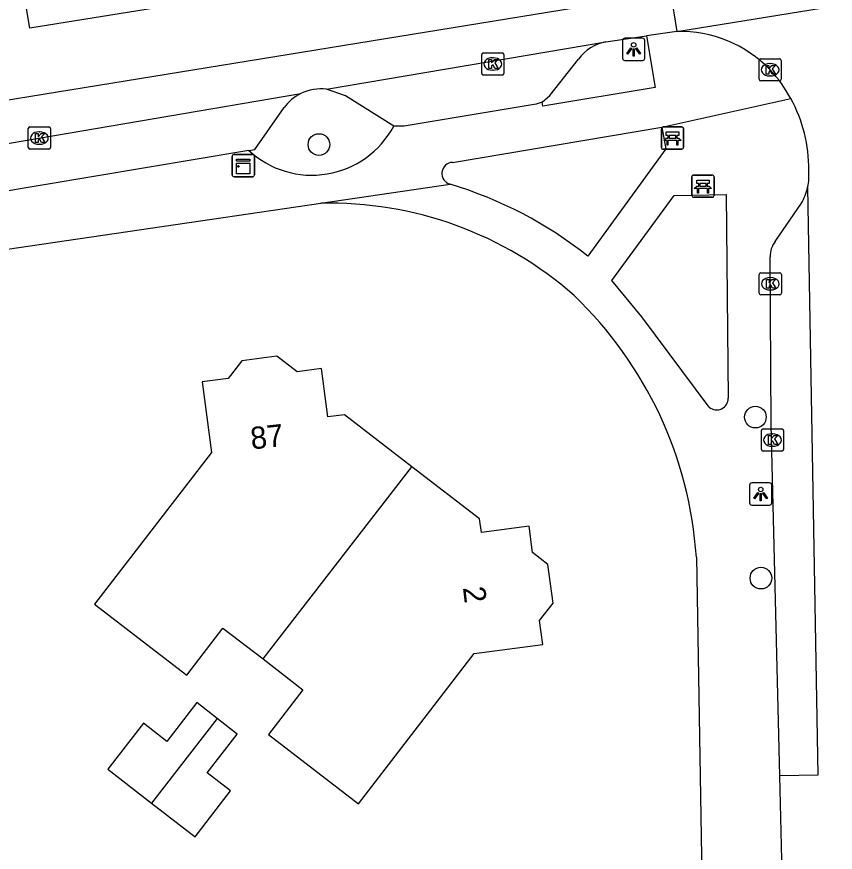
# Model space of a CAD drawing. Extents: x 161772 to 163123, y 383092 to 383917.
# Drawn here: x 162243.1 to 162280.01, y 383587.85 to 383625.53 of the extents above; entities that cross this region are included whole.
import ezdxf

# ---------------------------------------------------------------- set-up
doc = ezdxf.new("R2010")
doc.units = 0
for name, color, linetype in [('IMGEO_Bank', 7, 'Continuous'), ('IMGEO_Boom', 7, 'Continuous'), ('IMGEO_Kast', 7, 'Continuous'), ('IMGEO_Kolk', 7, 'Continuous'), ('IMGEO_Lichtpunt', 7, 'Continuous'), ('IMGEO_Pand', 7, 'Continuous'), ('IMGEO_Pand_nummerreeks', 7, 'Continuous'), ('IMGEO_Parkeervlak_open', 7, 'Continuous'), ('IMGEO_Rijbaan_lokaal_gesloten', 7, 'Continuous'), ('IMGEO_Voetpad_open', 7, 'Continuous')]:
    doc.layers.add(name, color=color, linetype=linetype)

msp = doc.modelspace()

# ---------------------------------------------------------------- linework, layer by layer
at = {"layer": 'IMGEO_Bank'}
for p, q in [((162272.166, 383619.631), (162272.166, 383620.472)), ((162272.166, 383620.472), (162272.166, 383619.631)), ((162272.241, 383620.556), (162273.082, 383620.556)), ((162273.082, 383620.556), (162272.241, 383620.556)), ((162273.166, 383620.481), (162273.166, 383619.64)), ((162273.166, 383619.64), (162273.166, 383620.481)), ((162272.475, 383620.062), (162272.475, 383620.168)), ((162272.519, 383620.168), (162272.519, 383620.062)), ((162272.807, 383620.174), (162272.525, 383620.174)), ((162272.525, 383620.056), (162272.807, 383620.056)), ((162272.813, 383620.062), (162272.813, 383620.168)), ((162272.857, 383620.168), (162272.857, 383620.062)), ((162272.863, 383619.954), (162272.47, 383619.954)), ((162273.091, 383619.556), (162272.25, 383619.556)), ((162272.25, 383619.556), (162273.091, 383619.556)), ((162273.54, 383617.46), (162273.54, 383618.301)), ((162273.54, 383618.301), (162273.54, 383617.46)), ((162273.615, 383618.385), (162274.456, 383618.385)), ((162274.456, 383618.385), (162273.615, 383618.385)), ((162274.54, 383618.31), (162274.54, 383617.469)), ((162274.54, 383617.469), (162274.54, 383618.31)), ((162274.237, 383617.783), (162273.844, 383617.783)), ((162273.849, 383617.891), (162273.849, 383617.997)), ((162273.893, 383617.997), (162273.893, 383617.891)), ((162274.181, 383618.003), (162273.899, 383618.003)), ((162273.899, 383617.885), (162274.181, 383617.885)), ((162274.187, 383617.891), (162274.187, 383617.997)), ((162274.231, 383617.997), (162274.231, 383617.891)), ((162274.465, 383617.385), (162273.624, 383617.385)), ((162273.624, 383617.385), (162274.465, 383617.385))]:
    msp.add_line(p, q, dxfattribs=at)
for points in [[(162272.413, 383619.954), (162272.271, 383619.954), (162272.383, 383620.056), (162272.469, 383620.056)], [(162272.469, 383620.174), (162272.383, 383620.174), (162272.383, 383620.335), (162272.946, 383620.335), (162272.946, 383620.174), (162272.863, 383620.174)], [(162272.863, 383620.056), (162272.946, 383620.056), (162273.058, 383619.954), (162272.919, 383619.954)], [(162272.463, 383619.947), (162272.463, 383619.74), (162272.42, 383619.74), (162272.42, 383619.947)], [(162272.913, 383619.947), (162272.913, 383619.74), (162272.869, 383619.74), (162272.869, 383619.947)], [(162273.843, 383618.003), (162273.757, 383618.003), (162273.757, 383618.164), (162274.32, 383618.164), (162274.32, 383618.003), (162274.237, 383618.003)], [(162273.787, 383617.783), (162273.645, 383617.783), (162273.757, 383617.885), (162273.843, 383617.885)], [(162273.837, 383617.776), (162273.837, 383617.569), (162273.794, 383617.569), (162273.794, 383617.776)], [(162274.237, 383617.885), (162274.32, 383617.885), (162274.432, 383617.783), (162274.293, 383617.783)], [(162274.287, 383617.776), (162274.287, 383617.569), (162274.243, 383617.569), (162274.243, 383617.776)]]:
    msp.add_lwpolyline(points, dxfattribs=at)
for centre, radius, start, end in [((162272.244, 383620.478), 0.0779, 92.4484, 184.2845), ((162272.244, 383620.478), 0.0779, 92.4484, 184.2845), ((162273.088, 383620.478), 0.0779, 2.4484, 94.2845), ((162273.088, 383620.478), 0.0779, 2.4484, 94.2845), ((162272.468, 383620.167), 0.00671, 2.8957, 87.1043), ((162272.468, 383620.063), 0.00671, 272.8957, 357.1043), ((162272.525, 383620.167), 0.00671, 92.8957, 177.1043), ((162272.525, 383620.063), 0.00671, 182.8957, 267.1043), ((162272.807, 383620.167), 0.00671, 2.8957, 87.1043), ((162272.807, 383620.063), 0.00671, 272.8957, 357.1043), ((162272.864, 383620.167), 0.00671, 92.8957, 177.1043), ((162272.864, 383620.063), 0.00671, 182.8957, 267.1043), ((162272.244, 383619.634), 0.0779, 182.4484, 274.2845), ((162272.244, 383619.634), 0.0779, 182.4484, 274.2845), ((162272.413, 383619.947), 0.00671, 2.8957, 87.1043), ((162272.47, 383619.947), 0.00671, 92.8957, 177.1043), ((162272.862, 383619.947), 0.00671, 2.8957, 87.1043), ((162272.919, 383619.947), 0.00671, 92.8957, 177.1043), ((162273.088, 383619.634), 0.0779, 272.4484, 4.2845), ((162273.088, 383619.634), 0.0779, 272.4484, 4.2845), ((162273.618, 383618.307), 0.0779, 92.4484, 184.2845), ((162273.618, 383618.307), 0.0779, 92.4484, 184.2845), ((162274.462, 383618.307), 0.0779, 2.4484, 94.2845), ((162274.462, 383618.307), 0.0779, 2.4484, 94.2845), ((162273.787, 383617.776), 0.00671, 2.8957, 87.1043), ((162273.844, 383617.776), 0.00671, 92.8957, 177.1043), ((162273.842, 383617.996), 0.00671, 2.8957, 87.1043), ((162273.842, 383617.892), 0.00671, 272.8957, 357.1043), ((162273.899, 383617.996), 0.00671, 92.8957, 177.1043), ((162273.899, 383617.892), 0.00671, 182.8957, 267.1043), ((162274.181, 383617.996), 0.00671, 2.8957, 87.1043), ((162274.181, 383617.892), 0.00671, 272.8957, 357.1043), ((162274.238, 383617.996), 0.00671, 92.8957, 177.1043), ((162274.238, 383617.892), 0.00671, 182.8957, 267.1043), ((162274.236, 383617.776), 0.00671, 2.8957, 87.1043), ((162274.293, 383617.776), 0.00671, 92.8957, 177.1043), ((162273.618, 383617.463), 0.0779, 182.4484, 274.2845), ((162273.618, 383617.463), 0.0779, 182.4484, 274.2845), ((162274.462, 383617.463), 0.0779, 272.4484, 4.2845), ((162274.462, 383617.463), 0.0779, 272.4484, 4.2845)]:
    msp.add_arc(centre, radius, start, end, dxfattribs=at)
at = {"layer": 'IMGEO_Boom'}
for centre in [(162256.725, 383619.765), (162276.403, 383607.472), (162276.656, 383600.211)]:
    msp.add_circle(centre, 0.489, dxfattribs=at)
at = {"layer": 'IMGEO_Kast'}
for p, q in [((162252.811, 383618.388), (162252.811, 383619.229)), ((162252.811, 383619.229), (162252.811, 383618.388)), ((162252.886, 383619.313), (162253.727, 383619.313)), ((162253.727, 383619.313), (162252.886, 383619.313)), ((162253.811, 383619.238), (162253.811, 383618.397)), ((162253.811, 383618.397), (162253.811, 383619.238)), ((162253.736, 383618.313), (162252.895, 383618.313)), ((162252.895, 383618.313), (162253.736, 383618.313))]:
    msp.add_line(p, q, dxfattribs=at)
for points in [[(162253.006, 383619.103), (162253.606, 383619.103), (162253.606, 383619.018), (162253.006, 383619.018), (162253.006, 383619.103)], [(162253.006, 383618.928), (162253.606, 383618.928), (162253.606, 383618.439), (162253.006, 383618.439), (162253.006, 383618.928)]]:
    msp.add_lwpolyline(points, dxfattribs=at)
msp.add_circle((162253.09, 383618.777), 0.0377, dxfattribs=at)
for centre, start, end in [((162252.889, 383619.235), 92.4484, 184.2845), ((162252.889, 383619.235), 92.4484, 184.2845), ((162253.733, 383619.235), 2.4484, 94.2845), ((162253.733, 383619.235), 2.4484, 94.2845), ((162252.889, 383618.391), 182.4484, 274.2845), ((162252.889, 383618.391), 182.4484, 274.2845), ((162253.733, 383618.391), 272.4484, 4.2845), ((162253.733, 383618.391), 272.4484, 4.2845)]:
    msp.add_arc(centre, 0.0779, start, end, dxfattribs=at)
at = {"layer": 'IMGEO_Kolk'}
for p, q in [((162264.065, 383622.971), (162264.065, 383623.823)), ((162264.14, 383623.897), (162264.992, 383623.897)), ((162265.066, 383623.823), (162265.066, 383622.971)), ((162264.553, 383623.677), (162264.578, 383623.677)), ((162276.568, 383622.71), (162276.568, 383623.562)), ((162276.643, 383623.636), (162277.495, 383623.636)), ((162277.056, 383623.416), (162277.081, 383623.416)), ((162277.569, 383623.562), (162277.569, 383622.71)), ((162264.576, 383623.117), (162264.551, 383623.117)), ((162264.992, 383622.897), (162264.14, 383622.897)), ((162277.495, 383622.636), (162276.643, 383622.636)), ((162277.079, 383622.856), (162277.054, 383622.856)), ((162243.618, 383619.632), (162243.618, 383620.484)), ((162243.693, 383620.558), (162244.545, 383620.558)), ((162244.619, 383620.484), (162244.619, 383619.632)), ((162244.106, 383620.338), (162244.131, 383620.338)), ((162244.129, 383619.778), (162244.104, 383619.778)), ((162244.545, 383619.558), (162243.693, 383619.558)), ((162276.653, 383613.985), (162277.505, 383613.985)), ((162276.578, 383613.059), (162276.578, 383613.911)), ((162277.066, 383613.765), (162277.091, 383613.765)), ((162277.579, 383613.911), (162277.579, 383613.059)), ((162277.089, 383613.205), (162277.064, 383613.205)), ((162277.505, 383612.985), (162276.653, 383612.985)), ((162276.673, 383606.012), (162276.673, 383606.864)), ((162276.748, 383606.938), (162277.6, 383606.938)), ((162277.674, 383606.864), (162277.674, 383606.012)), ((162277.161, 383606.718), (162277.186, 383606.718)), ((162277.184, 383606.158), (162277.159, 383606.158)), ((162277.6, 383605.938), (162276.748, 383605.938))]:
    msp.add_line(p, q, dxfattribs=at)
for points in [[(162264.065, 383622.971), (162264.065, 383623.823)], [(162264.14, 383623.897), (162264.992, 383623.897)], [(162265.066, 383623.823), (162265.066, 383622.971)], [(162264.386, 383623.597), (162264.509, 383623.597), (162264.509, 383623.446), (162264.639, 383623.597), (162264.803, 383623.597), (162264.657, 383623.446), (162264.81, 383623.197), (162264.658, 383623.197), (162264.573, 383623.361), (162264.509, 383623.294), (162264.509, 383623.197), (162264.386, 383623.197), (162264.386, 383623.597)], [(162276.568, 383622.71), (162276.568, 383623.562)], [(162276.643, 383623.636), (162277.495, 383623.636)], [(162277.569, 383623.562), (162277.569, 383622.71)], [(162276.889, 383623.336), (162277.012, 383623.336), (162277.012, 383623.185), (162277.142, 383623.336), (162277.306, 383623.336), (162277.16, 383623.185), (162277.313, 383622.936), (162277.161, 383622.936), (162277.076, 383623.1), (162277.012, 383623.033), (162277.012, 383622.936), (162276.889, 383622.936), (162276.889, 383623.336)], [(162264.992, 383622.897), (162264.14, 383622.897)], [(162277.495, 383622.636), (162276.643, 383622.636)], [(162243.618, 383619.632), (162243.618, 383620.484)], [(162243.693, 383620.558), (162244.545, 383620.558)], [(162244.619, 383620.484), (162244.619, 383619.632)], [(162243.939, 383620.258), (162244.062, 383620.258), (162244.062, 383620.107), (162244.192, 383620.258), (162244.356, 383620.258), (162244.21, 383620.107), (162244.363, 383619.858), (162244.211, 383619.858), (162244.126, 383620.022), (162244.062, 383619.955), (162244.062, 383619.858), (162243.939, 383619.858), (162243.939, 383620.258)], [(162244.545, 383619.558), (162243.693, 383619.558)], [(162276.653, 383613.985), (162277.505, 383613.985)], [(162276.578, 383613.059), (162276.578, 383613.911)], [(162276.899, 383613.685), (162277.022, 383613.685), (162277.022, 383613.534), (162277.152, 383613.685), (162277.316, 383613.685), (162277.17, 383613.534), (162277.323, 383613.285), (162277.171, 383613.285), (162277.086, 383613.449), (162277.022, 383613.382), (162277.022, 383613.285), (162276.899, 383613.285), (162276.899, 383613.685)], [(162277.579, 383613.911), (162277.579, 383613.059)], [(162277.505, 383612.985), (162276.653, 383612.985)], [(162276.673, 383606.012), (162276.673, 383606.864)], [(162276.748, 383606.938), (162277.6, 383606.938)], [(162277.674, 383606.864), (162277.674, 383606.012)], [(162276.994, 383606.638), (162277.117, 383606.638), (162277.117, 383606.487), (162277.247, 383606.638), (162277.411, 383606.638), (162277.265, 383606.487), (162277.418, 383606.238), (162277.266, 383606.238), (162277.181, 383606.402), (162277.117, 383606.335), (162277.117, 383606.238), (162276.994, 383606.238), (162276.994, 383606.638)], [(162277.6, 383605.938), (162276.748, 383605.938)]]:
    msp.add_lwpolyline(points, dxfattribs=at)
for centre, start, end in [((162264.142, 383623.821), 91.552, 178.448), ((162264.142, 383623.821), 91.552, 178.448), ((162264.99, 383623.821), 1.552, 88.448), ((162264.99, 383623.821), 1.552, 88.448), ((162276.645, 383623.56), 91.552, 178.448), ((162276.645, 383623.56), 91.552, 178.448), ((162277.493, 383623.56), 1.552, 88.448), ((162277.493, 383623.56), 1.552, 88.448), ((162264.142, 383622.973), 181.552, 268.448), ((162264.142, 383622.973), 181.552, 268.448), ((162264.99, 383622.973), 271.552, 358.448), ((162264.99, 383622.973), 271.552, 358.448), ((162276.645, 383622.712), 181.552, 268.448), ((162276.645, 383622.712), 181.552, 268.448), ((162277.493, 383622.712), 271.552, 358.448), ((162277.493, 383622.712), 271.552, 358.448), ((162243.695, 383620.482), 91.552, 178.448), ((162243.695, 383620.482), 91.552, 178.448), ((162244.543, 383620.482), 1.552, 88.448), ((162244.543, 383620.482), 1.552, 88.448), ((162243.695, 383619.634), 181.552, 268.448), ((162243.695, 383619.634), 181.552, 268.448), ((162244.543, 383619.634), 271.552, 358.448), ((162244.543, 383619.634), 271.552, 358.448), ((162276.655, 383613.909), 91.552, 178.448), ((162276.655, 383613.909), 91.552, 178.448), ((162277.503, 383613.909), 1.552, 88.448), ((162277.503, 383613.909), 1.552, 88.448), ((162276.655, 383613.061), 181.552, 268.448), ((162276.655, 383613.061), 181.552, 268.448), ((162277.503, 383613.061), 271.552, 358.448), ((162277.503, 383613.061), 271.552, 358.448), ((162276.75, 383606.862), 91.552, 178.448), ((162276.75, 383606.862), 91.552, 178.448), ((162277.598, 383606.862), 1.552, 88.448), ((162277.598, 383606.862), 1.552, 88.448), ((162276.75, 383606.014), 181.552, 268.448), ((162276.75, 383606.014), 181.552, 268.448), ((162277.598, 383606.014), 271.552, 358.448), ((162277.598, 383606.014), 271.552, 358.448)]:
    msp.add_arc(centre, 0.0765, start, end, dxfattribs=at)
for centre, major_axis, ratio, start_param, end_param in [((162264.552, 383623.397), (-0.387, 0.002), 0.722429, 4.712389, 7.853982), ((162264.577, 383623.397), (-0.39, 0.002), 0.717154, 1.570796, 4.712389), ((162277.055, 383623.136), (-0.387, 0.002), 0.722429, 4.712389, 7.853982), ((162277.08, 383623.136), (-0.39, 0.002), 0.717154, 1.570796, 4.712389), ((162244.105, 383620.058), (-0.387, 0.002), 0.722429, 4.712389, 7.853982), ((162244.13, 383620.058), (-0.39, 0.002), 0.717154, 1.570796, 4.712389), ((162277.065, 383613.485), (-0.387, 0.002), 0.722429, 4.712389, 7.853982), ((162277.09, 383613.485), (-0.39, 0.002), 0.717154, 1.570796, 4.712389), ((162277.16, 383606.438), (-0.387, 0.002), 0.722429, 4.712389, 7.853982), ((162277.185, 383606.438), (-0.39, 0.002), 0.717154, 1.570796, 4.712389)]:
    msp.add_ellipse(centre, major_axis=major_axis, ratio=ratio, start_param=start_param, end_param=end_param, dxfattribs=at)
at = {"layer": 'IMGEO_Lichtpunt'}
for p, q in [((162271.318, 383624.558), (162270.51, 383624.558)), ((162271.318, 383624.558), (162270.51, 383624.558)), ((162270.416, 383624.463), (162270.416, 383623.656)), ((162270.416, 383624.463), (162270.416, 383623.656)), ((162271.412, 383623.656), (162271.412, 383624.463)), ((162271.412, 383623.656), (162271.412, 383624.463)), ((162270.51, 383623.562), (162271.318, 383623.562)), ((162270.51, 383623.562), (162271.318, 383623.562)), ((162276.145, 383604.409), (162276.145, 383603.602)), ((162276.145, 383604.409), (162276.145, 383603.602)), ((162277.047, 383604.504), (162276.239, 383604.504)), ((162277.047, 383604.504), (162276.239, 383604.504)), ((162277.141, 383603.602), (162277.141, 383604.409)), ((162277.141, 383603.602), (162277.141, 383604.409)), ((162276.239, 383603.508), (162277.047, 383603.508)), ((162276.239, 383603.508), (162277.047, 383603.508))]:
    msp.add_line(p, q, dxfattribs=at)
for points in [[(162270.79, 383624.127), (162270.829, 383624.099), (162270.641, 383623.837), (162270.603, 383623.864), (162270.79, 383624.127)], [(162271.002, 383624.099), (162271.04, 383624.126), (162271.227, 383623.864), (162271.188, 383623.836), (162271.002, 383624.099)], [(162270.892, 383624.079), (162270.939, 383624.079), (162270.939, 383623.757), (162270.892, 383623.757), (162270.892, 383624.079)], [(162276.519, 383604.073), (162276.558, 383604.045), (162276.37, 383603.783), (162276.332, 383603.81), (162276.519, 383604.073)], [(162276.621, 383604.025), (162276.668, 383604.025), (162276.668, 383603.703), (162276.621, 383603.703), (162276.621, 383604.025)], [(162276.731, 383604.045), (162276.769, 383604.072), (162276.956, 383603.81), (162276.917, 383603.782), (162276.731, 383604.045)]]:
    msp.add_lwpolyline(points, dxfattribs=at)
for centre in [(162270.915, 383624.261), (162276.644, 383604.207)]:
    msp.add_circle(centre, 0.0994, dxfattribs=at)
for centre, start, end in [((162270.51, 383624.463), 90, 180), ((162270.51, 383624.463), 90, 180), ((162271.318, 383624.463), 0, 90), ((162271.318, 383624.463), 0, 90), ((162270.51, 383623.656), 180, 270), ((162270.51, 383623.656), 180, 270), ((162271.318, 383623.656), 270, 0), ((162271.318, 383623.656), 270, 360), ((162276.239, 383604.409), 90, 180), ((162276.239, 383604.409), 90, 180), ((162277.047, 383604.409), 0, 90), ((162277.047, 383604.409), 0, 90), ((162276.239, 383603.602), 180, 270), ((162276.239, 383603.602), 180, 270), ((162277.047, 383603.602), 270, 0), ((162277.047, 383603.602), 270, 360)]:
    msp.add_arc(centre, 0.0946, start, end, dxfattribs=at)
at = {"layer": 'IMGEO_Pand'}
for points in [[(162260.914, 383605.234), (162257.87, 383607.576), (162257.126, 383607.479), (162256.841, 383609.662), (162255.74, 383609.519), (162254.827, 383610.221), (162253.24, 383610.014), (162252.624, 383609.214), (162251.457, 383609.062), (162251.872, 383605.882), (162246.606, 383599.037), (162250.76, 383595.841), (162252.39, 383597.959), (162254.201, 383596.565)], [(162254.201, 383596.565), (162260.914, 383605.234)], [(162254.201, 383596.565), (162256.003, 383595.177), (162254.447, 383593.156), (162258.504, 383590.033), (162263.724, 383596.818), (162266.814, 383597.221), (162266.674, 383598.293), (162267.279, 383599.08), (162267.051, 383600.826), (162266.353, 383601.363), (162266.198, 383602.552), (162264.051, 383602.272), (162263.971, 383602.882), (162260.914, 383605.234)], [(162252.127, 383593.886), (162251.212, 383594.595), (162249.858, 383592.847), (162248.805, 383593.662), (162247.203, 383591.593), (162249.171, 383590.069)], [(162252.127, 383593.886), (162249.171, 383590.069)], [(162249.171, 383590.069), (162251.139, 383588.545), (162252.741, 383590.614), (162251.688, 383591.429), (162253.042, 383593.178), (162252.127, 383593.886)]]:
    msp.add_lwpolyline(points, dxfattribs=at)
at = {"layer": 'IMGEO_Parkeervlak_open'}
for points in [[(162266.792, 383621.683), (162267.141, 383621.977), (162268.427, 383623.619)], [(162260.096, 383620.592), (162257.922, 383621.958), (162257.069, 383622.26)], [(162253.557, 383619.501), (162253.833, 383619.548), (162255.15, 383621.429)]]:
    msp.add_lwpolyline(points, dxfattribs=at)
for centre, radius, start, end in [((162270.05, 383622.42), 2.018, 101.0827, 143.5349), ((162256.828, 383620.19), 2.086, 116.173, 143.557)]:
    msp.add_arc(centre, radius, start, end, dxfattribs=at)
at = {"layer": 'IMGEO_Rijbaan_lokaal_gesloten'}
for points in [[(162308.33, 383637.502), (162308.644, 383635.717), (162289.263, 383632.424), (162269.16, 383629.116), (162243.686, 383625.013), (162243.382, 383626.82)], [(162272.867, 383624.864), (162289.596, 383627.588)], [(162218.542, 383618.178), (162232.617, 383620.137), (162272.581, 383626.655), (162272.867, 383624.864)], [(162269.662, 383624.4), (162271.493, 383624.665)], [(162272.867, 383624.864), (162271.493, 383624.665)], [(162257.069, 383622.26), (162269.662, 383624.4)], [(162238.078, 383619.032), (162255.908, 383622.062)], [(162278.761, 383617.831), (162279.221, 383591.317), (162277.506, 383591.288)], [(162277.677, 383584.356), (162277.506, 383591.288)]]:
    msp.add_lwpolyline(points, dxfattribs=at)
for centre, radius, start, end in [((162273.006, 383619.229), 5.637, 43.8808, 91.4111), ((162272.266, 383618.698), 6.539, 28.6901, 42.7433), ((162256.823, 383620.198), 2.077, 83.2052, 116.1513), ((162272.225, 383618.678), 6.585, 359.3253, 28.6722), ((162276.375, 383618.369), 2.446, 347.2916, 5.4166)]:
    msp.add_arc(centre, radius, start, end, dxfattribs=at)
at = {"layer": 'IMGEO_Voetpad_open'}
for points in [[(162271.493, 383624.665), (162271.88, 383622.33), (162266.823, 383621.496), (162266.792, 383621.683)], [(162266.792, 383621.683), (162266.524, 383621.585), (162260.559, 383620.586), (162260.096, 383620.592)], [(162272.188, 383620.541), (162278.003, 383621.837)], [(162262.752, 383618.962), (162272.188, 383620.541)], [(162272.188, 383620.541), (162272.372, 383619.568), (162268.853, 383614.73)], [(162253.557, 383619.501), (162241.899, 383617.541), (162241.581, 383617.555), (162241.194, 383617.69), (162239.471, 383618.705)], [(162256.802, 383617.115), (162262.641, 383617.973)], [(162274.325, 383607.927), (162271.281, 383611.992), (162269.924, 383613.627), (162272.736, 383617.465), (162275.085, 383617.513), (162275.174, 383608.328)], [(162147.874, 383613.435), (162207.733, 383611.15), (162209.591, 383611.164), (162215.124, 383611.45), (162220.638, 383611.986), (162235.499, 383613.996), (162256.802, 383617.115)], [(162277.302, 383615.389), (162278.477, 383617.114)], [(162277.506, 383591.288), (162277.113, 383607.159), (162277.072, 383614.703)], [(162273.743, 383601.16), (162274.444, 383559.797), (162274.609, 383542.395)]]:
    msp.add_lwpolyline(points, dxfattribs=at)
for centre, radius, start, end in [((162256.406, 383622.568), 4.186, 227.1074, 331.8371), ((162262.771, 383618.459), 0.503, 92.1783, 255.0142), ((162257.334, 383600.236), 18.514, 51.5239, 73.3421), ((162276.349, 383618.371), 2.471, 329.4154, 347.3681), ((162257.212, 383600.45), 16.67, 48.6186, 91.4096), ((162278.076, 383614.748), 1.005, 140.371, 182.5588), ((162255.739, 383599.936), 18.045, 3.888, 46.1878), ((162274.662, 383608.312), 0.512, 228.7503, 1.8144)]:
    msp.add_arc(centre, radius, start, end, dxfattribs=at)

# ---------------------------------------------------------------- texts
at = {"layer": 'IMGEO_Pand_nummerreeks'}
for s, rotation, p in [('87', 6.3589, (162253.69, 383606.011)), ('2', 276.5913, (162263.215, 383599.786))]:
    msp.add_text(s, height=1, rotation=rotation, dxfattribs=at).set_placement(p)

doc.saveas('drawing.dxf')
